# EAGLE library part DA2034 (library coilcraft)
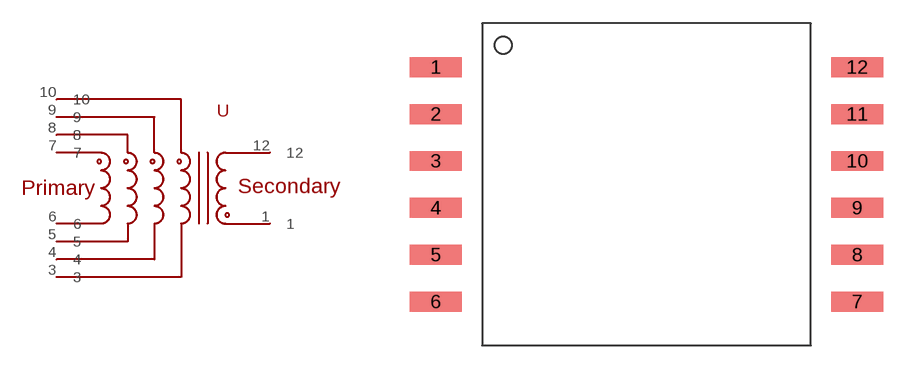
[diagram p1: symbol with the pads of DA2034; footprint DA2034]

Designator prefix -

## DA2034  [DA2034]
1  1
3  3
4  4
5  5
6  6
7  7
8  8
9  9
10  10
12  12

## Footprint DA2034 (pad centres in mm)
smd 3.302 x 1.27: 1 -13.462,7.493; 2 -13.462,4.496; 3 -13.462,1.499; 4 -13.462,-1.499; 5 -13.462,-4.496; 6 -13.462,-7.493; 7 13.462,-7.493; 8 13.462,-4.496; 9 13.462,-1.499; 10 13.462,1.499; 11 13.462,4.496; 12 13.462,7.493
